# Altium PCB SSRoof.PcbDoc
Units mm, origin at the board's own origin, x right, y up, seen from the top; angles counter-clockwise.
Board outline 100 x 115 mm, 2 copper layers (Top Layer, Bottom Layer); 93 components, 75 nets, 327 pads, 36 vias.
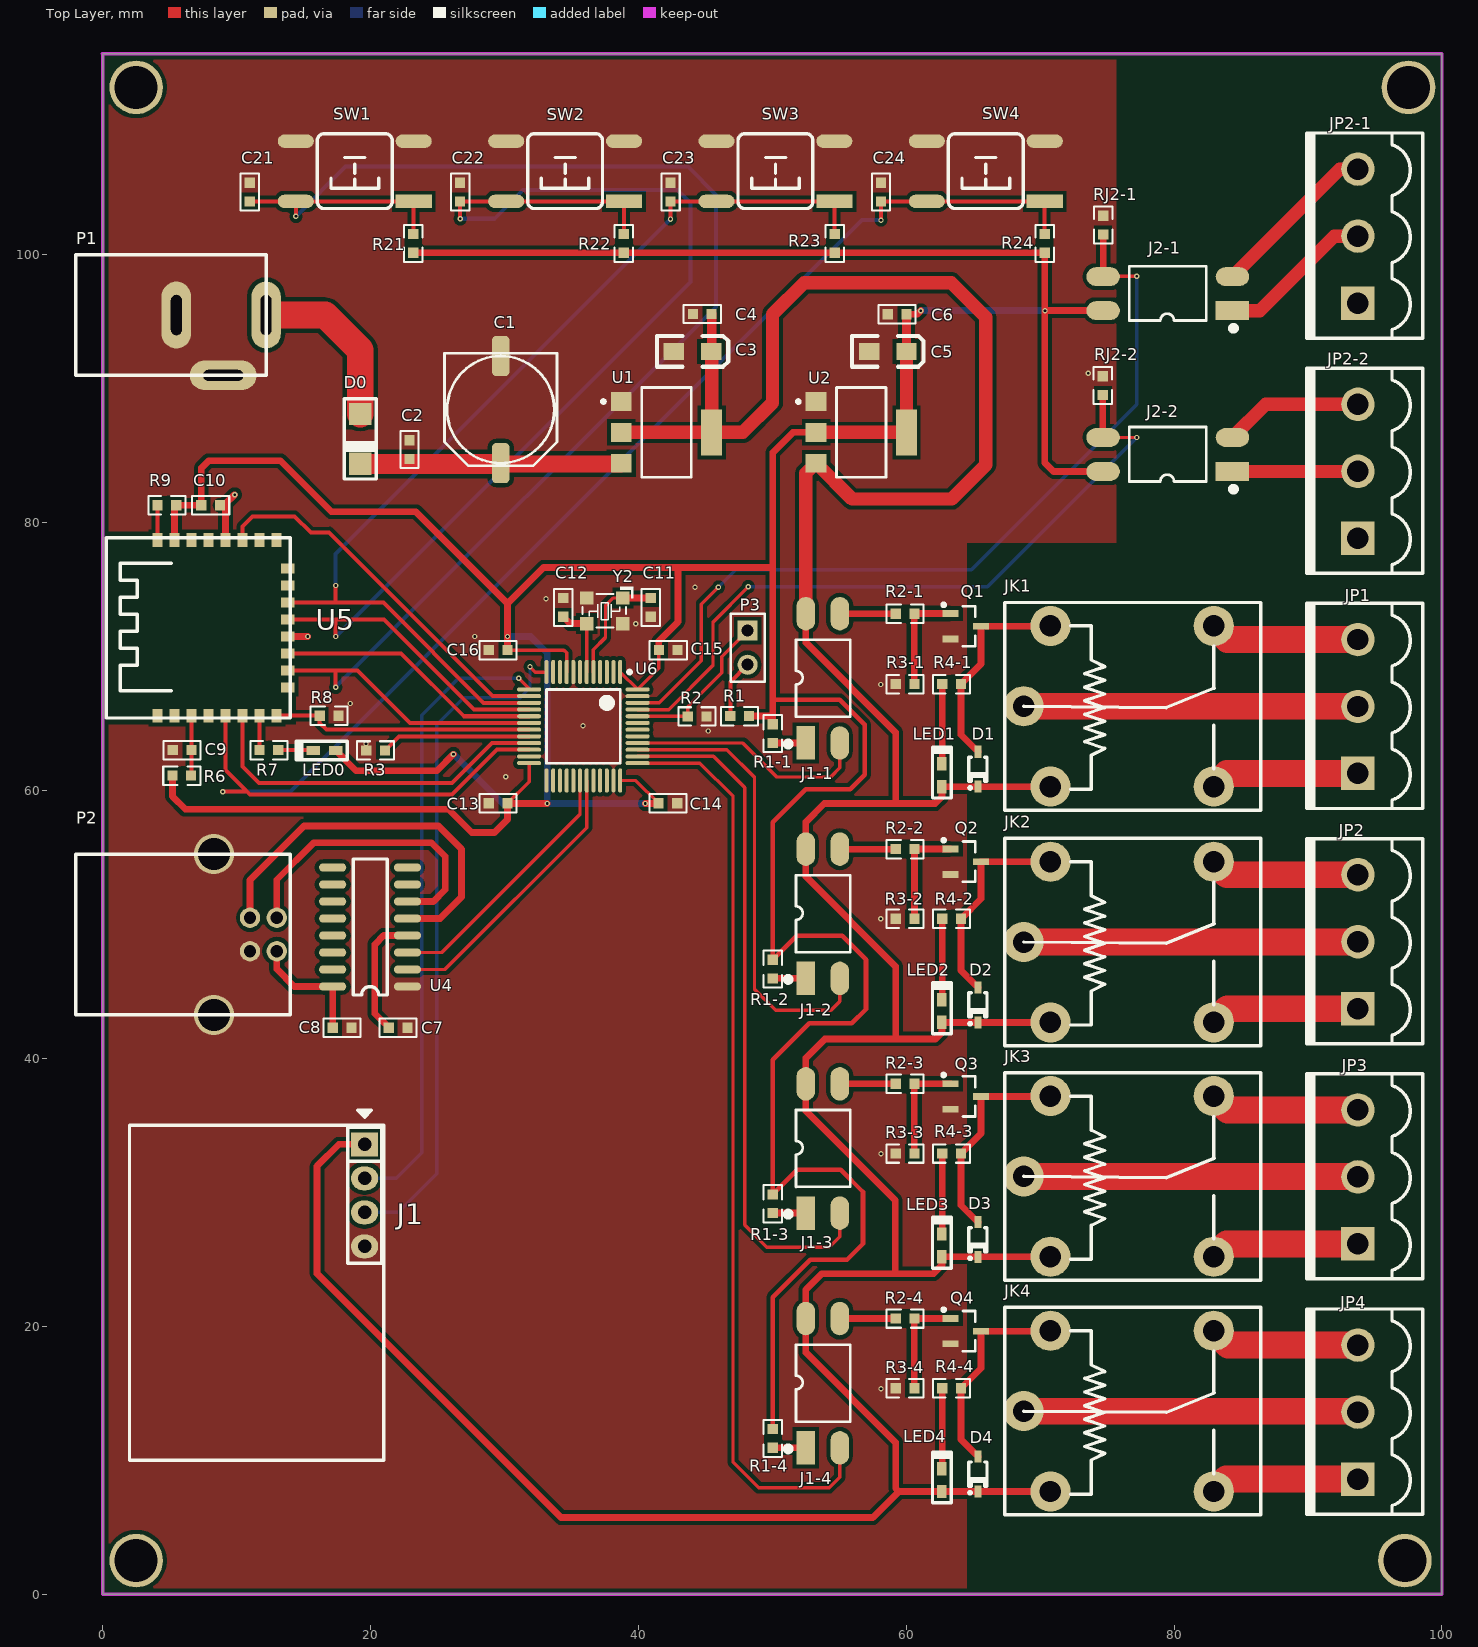
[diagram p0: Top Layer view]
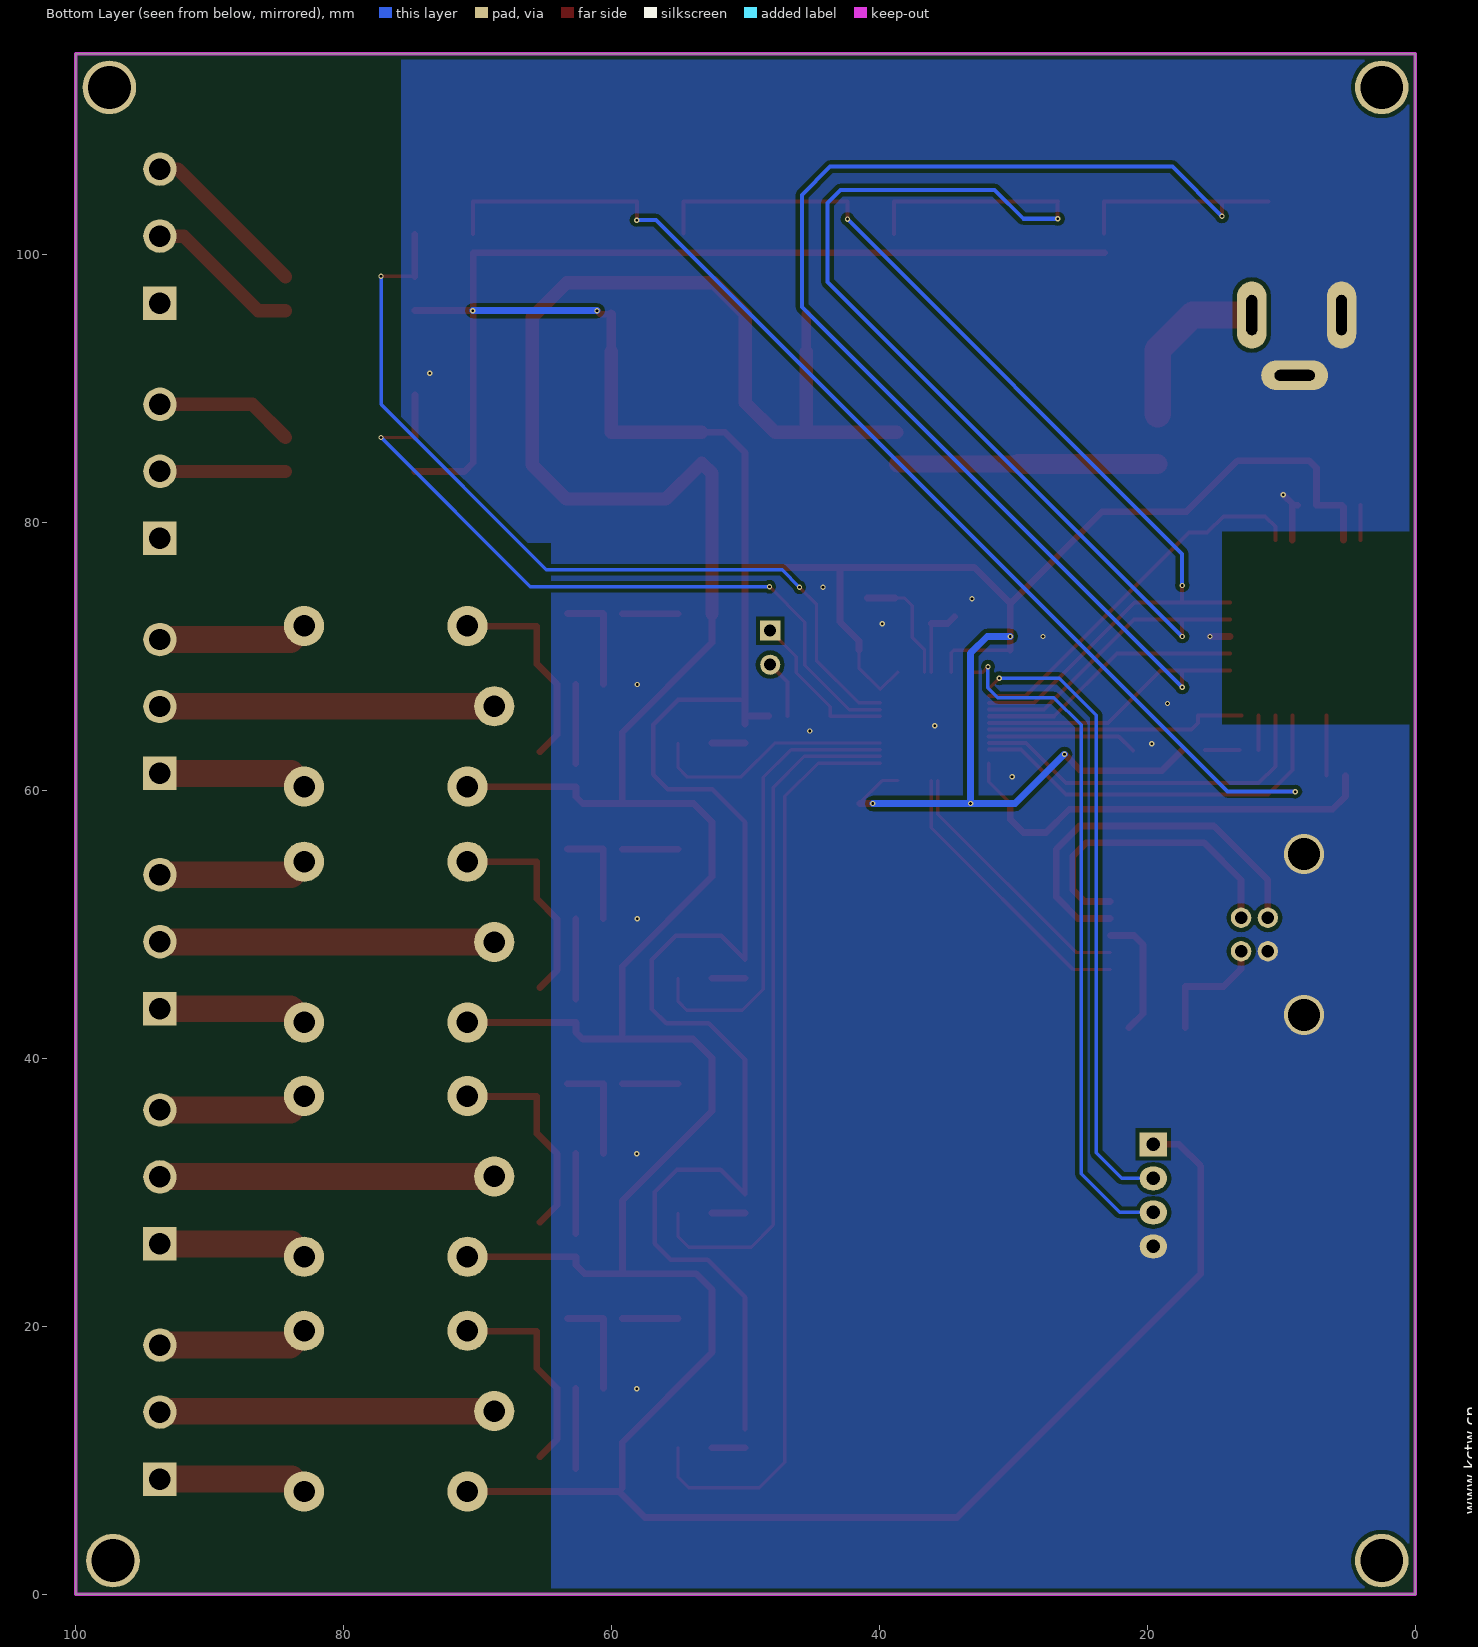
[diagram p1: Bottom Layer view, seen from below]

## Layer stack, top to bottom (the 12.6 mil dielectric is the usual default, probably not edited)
Top Solder: solder mask 0.0102, Solder Resist, Dk 3.5
Top Layer: signal copper 0.0356
Dielectric1: dielectric 0.32, FR-4, Dk 4.8
Bottom Layer: signal copper 0.0356
Bottom Solder: solder mask 0.0102, Solder Resist, Dk 3.5

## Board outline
0,0 0,115 100,115 100,0

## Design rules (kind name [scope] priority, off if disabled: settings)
Clearance Clearance_pyog [InPolygon] p1: gap=0.305
Clearance Clearance_mcu [InComponentClass('U7')] p2: gap=0.178
Clearance [All] p3: gap=0.178
HoleSize [All] p1: absolutevalues=TRUE maxlimit=25.4 minlimit=0.025 maxpercent=80.000 minpercent=20.000
MinimumSolderMaskSliver [All] p1: minsoldermaskwidth=0
PolygonConnect GNDVIA [IsVia] p1: connectstyle=Direct reliefconductorwidth=0.254 reliefentries=4 polygonreliefangle="90 Angle" airgapwidth=0.254
PolygonConnect [All] p2: connectstyle=Direct reliefconductorwidth=0.254 reliefentries=4 polygonreliefangle="90 Angle" airgapwidth=0.254
RoutingVias [All] p1: holewidth=0.711 width=1.27 viastyle="Through Hole" minholewidth=0.3 minwidth=0.45 maxholewidth=0.711 maxwidth=1.27
SilkToSilkClearance [All] p1: silktosilkclearance=0
SilkToSolderMaskClearance [IsPad] p1: minsilkscreentomaskgap=0 clearancetoexposedcopper=TRUE
SolderMaskExpansion [All] p1: expansion=0.102
Width [All] p1: maxlimit=3 minlimit=0.254 preferedwidth=0.254
25 further rules are at their usual default settings.

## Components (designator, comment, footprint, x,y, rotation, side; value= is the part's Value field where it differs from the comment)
C1 "470uF" CAP8 29.718,88.443 r90 top
C2 "100nF" 0603C 22.911,86.157 r270 top
C3 "10uF" 3216 45.441,92.786 r0 top
C4 "100nF" 0603C 44.069,95.58 r0 top
C5 "10uF" 3216 60.02,92.786 r0 top
C6 "100nF" 0603C 58.623,95.555 r0 top
C7 "100nF" 0603C 22.758,42.291 r180 top
C8 "100nF" 0603C 18.567,42.291 r180 top
C9 "100nF" 0603C 6.629,63.017 r180 top
C10 "100nF" 0603C 7.366,81.305 r0 top
C11 "20pF" 0603C 40.919,74.371 r270 top
C12 "20pF" 0603C 34.392,72.974 r90 top
C13 "100nF" 0603C 28.829,59.055 r0 top
C14 "100nF" 0603C 42.901,59.055 r180 top
C15 "100nF" 0603C 42.926,70.485 r180 top
C16 "100nF" 0603C 28.829,70.485 r0 top
C21 "1nF" 0603C 10.973,103.988 r90 top
C22 "1nF" 0603C 26.687,103.988 r90 top
C23 "1nF" 0603C 42.401,103.988 r90 top
C24 "1nF" 0603C 58.115,103.988 r90 top
D0 "M7" DO-214AC 19.228,86.258 r270 top
D1 "1N4148" SOD-323 65.354,61.595 r270 top
D2 "1N4148" SOD-323 65.354,43.993 r270 top
D3 "1N4148" SOD-323 65.354,26.467 r270 top
D4 "1N4148" SOD-323 65.354,8.966 r270 top
J1 "YS-RF34T" PIN-4-2.54-1.0 19.558,29.769 r270 top
J1-1 "TLP521-1" SOP4-W2.54_M 53.772,68.377 r90 top
J1-2 "TLP521-1" SOP4-W2.54_M 53.772,50.8 r90 top
J1-3 "TLP521-1" SOP4-W2.54_M 53.772,33.274 r90 top
J1-4 "TLP521-1" SOP4-W2.54_M 53.772,15.748 r90 top
J2-1 "TLP521-1" SOP4-W2.54_M 79.527,97.104 r180 top
J2-2 "TLP521-1" SOP4-W2.54_M 79.527,85.09 r180 top
JK1 "SRD-05VDC-SL-C" SRD-C_B 70.764,72.288 r0 top
JK2 "SRD-05VDC-SL-C" SRD-C_B 70.764,54.686 r0 top
JK3 "SRD-05VDC-SL-C" SRD-C_B 70.764,37.186 r0 top
JK4 "SRD-05VDC-SL-C" SRD-C_B 70.764,19.66 r0 top
JP1 "HDR-1X3" KF2EDGK5.0-LI-3P 93.726,66.274 r90 top
JP2 "HDR-1X3" KF2EDGK5.0-LI-3P 93.726,48.712 r90 top
JP2-1 "HDR-1X3" KF2EDGK5.0-LI-3P 93.726,101.397 r90 top
JP2-2 "HDR-1X3" KF2EDGK5.0-LI-3P 93.726,83.835 r90 top (schematic designator JP2-24)
JP3 "HDR-1X3" KF2EDGK5.0-LI-3P 93.726,31.151 r90 top
JP4 "HDR-1X3" KF2EDGK5.0-LI-3P 93.726,13.589 r90 top
LED0 "LED" LED-0603 16.561,62.992 r180 top
LED1 "LED" LED-0603 62.662,61.138 r90 top
LED2 "LED" LED-0603 62.662,43.536 r90 top
LED3 "LED" LED-0603 62.662,26.035 r90 top
LED4 "LED" LED-0603 62.662,8.509 r90 top
P1 "SOURCE" DC_5.5MM -2,100 r0 top
P2 "USB-B" USB-B 13,48 r0 top
P3 "BOOT0" HDR1X2 48.158,71.933 r270 top
Q1 "SS8050" SOT23-3N 64.44,72.263 r270 top
Q2 "SS8050" SOT23-3N 64.44,54.686 r270 top
Q3 "SS8050" SOT23-3N 64.44,37.16 r270 top
Q4 "SS8050" SOT23-3N 64.44,19.634 r270 top
R1 "4.7K" 0603R 46.863,65.557 r0 top
R1-1 "2K" 0603R 50.038,63.551 r90 top
R1-2 "2K" 0603R 50.038,45.974 r90 top
R1-3 "2K" 0603R 50.038,28.448 r90 top
R1-4 "2K" 0603R 50.038,10.922 r90 top
R2 "10K" 0603R 43.688,65.532 r0 top
R2-1 "1K" 0603R 60.604,73.203 r180 top
R2-2 "1K" 0603R 60.604,55.626 r180 top
R2-3 "1K" 0603R 60.604,38.1 r180 top
R2-4 "1K" 0603R 60.604,20.574 r180 top
R3 "10K" 0603R 19.685,62.992 r0 top
R3-1 "4.7K" 0603R 59.207,67.945 r0 top
R3-2 "4.7K" 0603R 59.207,50.419 r0 top
R3-3 "4.7K" 0603R 59.207,32.893 r0 top
R3-4 "4.7K" 0603R 59.207,15.367 r0 top
R4-1 "5K" 0603R 62.687,67.945 r0 top
R4-2 "5K" 0603R 62.687,50.419 r0 top
R4-3 "5K" 0603R 62.687,32.893 r0 top
R4-4 "5K" 0603R 62.687,15.367 r0 top
R6 "10K" 0603R 6.604,61.112 r180 top
R7 "1K" 0603R 11.709,63.017 r0 top
R8 "4.7K" 0603R 17.602,65.583 r180 top
R9 "10K" 0603R 4.089,81.305 r0 top
R21 "10K" 0603R 23.19,101.549 r270 top
R22 "10K" 0603R 38.913,101.549 r270 top
R23 "10K" 0603R 54.661,101.549 r270 top
R24 "10K" 0603R 70.333,101.549 r270 top
RJ2-1 "1K" 0603R 74.701,102.921 r270 top
RJ2-2 "1K" 0603R 74.676,90.932 r270 top
SW1 "6x6x5" "TSW SMD-6*6*6" 18.821,106.248 r180 top
SW2 "6x6x5" "TSW SMD-6*6*6" 34.527,106.248 r180 top
SW3 "6x6x5" "TSW SMD-6*6*6" 50.233,106.248 r180 top
SW4 "6x6x5" "TSW SMD-6*6*6" 65.938,106.248 r180 top
U1 "AMS1117-5.0" SOT223 42.088,86.741 r270 top
U2 "AMS1117-3.3" SOT223 56.642,86.741 r270 top
U4 "CH340C" SO-16 22.758,45.364 r180 top
U5 "PSF-B04" PSF-B04 14,78.873 r180 top
U6 "STM32F103C8T6" LQFP48_N 35.89,64.795 r180 top
Y2 "8MHz  无源" X3225 38.811,74.397 r180 top

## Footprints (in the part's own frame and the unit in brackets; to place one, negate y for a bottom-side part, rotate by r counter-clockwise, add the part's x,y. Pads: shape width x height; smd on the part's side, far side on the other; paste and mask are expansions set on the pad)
0603C [mil]
  rect 30x30 smd: 1(0,0) 2(55,0)
  silkscreen extent -27,-27 82,27, body extent -4,-16 59,16, height 12
0603R [mil]
  rect 30x30 smd: 1(0,0) 2(55,0)
  silkscreen extent -27,-27 82,27, body extent -4,-18 58,16, height 18
3216 [mil]
  rect 60x50 smd: 1(0,0) 2(-110,0)
  silkscreen extent -160,-45 50,45, body extent -151,-35 38,36, height 73
CAP8 [mm] "直径8mm（蒜米工坊）"
  rrect50% 3x1.3 smd: 1(-4,0) 2(4,0)
  silkscreen extent -4.2,-4.2 4.2,4.2, body extent -4.52,-4.22 4.48,4.08, height 10.5
DC_5.5MM [mm]
  oval 2.2x5 hole 0.8 slot 3 at 90 deg: 1(14.2,-4.5) 2(7.5,-4.5)
  oval 5x2.2 hole 0.8 slot 3 at 0 deg: 3(11,-9)
  silkscreen extent 0,-9 14.2,0, body extent -0.1,-8.88 14.1,-0.12, height 10.82
DO-214AC [mm]
  rect 1.655x1.67 smd: 1(1.865,0) 2(-1.865,0)
  silkscreen extent -3,-1.2 3,1.2, body extent -2.74,-1.4 2.74,1.4, height 2.3
HDR1X2 [mm] "Connector; Header; 2 Position"
  rect 1.5x1.5 hole 0.9: 1(0,0)
  round 1.5 hole 0.9: 2(2.54,0)
  silkscreen extent -1.27,-1.27 3.81,1.27, body extent -1.27,-1.27 3.81,1.27, height 7.58
KF2EDGK5.0-LI-3P [mm] "立插端子"
  rect 2.5x2.5 hole 1.6: 1(-5,0)
  round 2.5 hole 1.6: 2(0,0) 3(5,0)
  silkscreen extent -7.62,-4.83 7.7,3.81, body extent -7.54,-4.75 7.54,3.75, height 11.25
LED-0603 [mm] "LED, SMD, 0603"
  rect 1x0.7 smd: 1(-0.85,0) 2(0.85,0)
  silkscreen extent -1.7,-0.7 2.1,0.7, body extent -1.03,-0.46 1.03,0.45, height 0.85
LQFP48_N [mm]
  oval 0.3x1.8 smd: 1(-2.75,-4.05) 2(-2.25,-4.05) 3(-1.75,-4.05) 4(-1.25,-4.05) 5(-0.75,-4.05) 6(-0.25,-4.05) 7(0.25,-4.05) 8(0.75,-4.05) 9(1.25,-4.05) 10(1.75,-4.05) 11(2.25,-4.05) 12(2.75,-4.05) 25(2.75,4.05) 26(2.25,4.05) 27(1.75,4.05) 28(1.25,4.05) 29(0.75,4.05) 30(0.25,4.05) 31(-0.25,4.05) 32(-0.75,4.05) 33(-1.25,4.05) 34(-1.75,4.05) 35(-2.25,4.05) 36(-2.75,4.05)
  oval 1.8x0.3 smd: 13(4.05,-2.75) 14(4.05,-2.25) 15(4.05,-1.75) 16(4.05,-1.25) 17(4.05,-0.75) 18(4.05,-0.25) 19(4.05,0.25) 20(4.05,0.75) 21(4.05,1.25) 22(4.05,1.75) 23(4.05,2.25) 24(4.05,2.75) 37(-4.05,2.75) 38(-4.05,2.25) 39(-4.05,1.75) 40(-4.05,1.25) 41(-4.05,0.75) 42(-4.05,0.25) 43(-4.05,-0.25) 44(-4.05,-0.75) 45(-4.05,-1.25) 46(-4.05,-1.75) 47(-4.05,-2.25) 48(-4.05,-2.75)
  silkscreen extent -3.58,-4.17 2.75,2.75, body extent -4.5,-4.5 4.5,4.5, height 1.5
PIN-4-2.54-1.0 [mil] "Pin Header"
  rect 70x80 hole 39.37: 1(-150,0)
  oval 70x80 hole 39.37: 2(-50,0) 3(50,0) 4(150,0)
  silkscreen extent -250,-50 200,50, body extent -200,-50 200,50, height 398
PSF-B04 [mm] "物联网开关芯片"
  rect 0.76x1.02 smd: 1(9.91,13.29) 2(8.64,13.29) 3(7.37,13.29) 4(6.1,13.29) 5(4.83,13.29) 6(3.56,13.29) 7(2.29,13.29) 8(1.02,13.29) 17(1.02,0.17) 18(2.29,0.17) 19(3.56,0.17) 20(4.83,0.17) 21(6.1,0.17) 22(7.37,0.17) 23(8.64,0.17) 24(9.91,0.17)
  rect 1.02x0.76 smd: 9(0.17,11.18) 10(0.17,9.91) 11(0.17,8.64) 12(0.17,7.37) 13(0.17,6.1) 14(0.17,4.83) 15(0.17,3.56) 16(0.17,2.29)
  silkscreen extent 0,0 13.72,13.46
SO-16 [mil]
  oval 80x24 smd: 1(0,0) 2(0,-50) 3(0,-100) 4(0,-150) 5(0,-200) 6(0,-250) 7(0,-300) 8(0,-350) 9(220,-350) 10(220,-300) 11(220,-250) 12(220,-200) 13(220,-150) 14(220,-100) 15(220,-50) 16(220,0)
  silkscreen extent 60,-375 160,25, body extent -12,-377 226,29, height 77
SOD-323 [mm] "SOD-323"
  rect 0.9x0.5 smd: 1(-1.3,0) 2(1.3,0)
  silkscreen extent -0.9,-0.67 1.49,0.67, body extent -1.35,-0.62 1.35,0.63, height 1.1
SOP4-W2.54_M [mm] "6.5*4.58*3.5mm（长宽高）"
  rect 2.5x1.4 smd: 1(-4.826,1.27)
  oval 2.5x1.4 smd: 2(-4.826,-1.27) 3(4.826,-1.27) 4(4.826,1.27)
  silkscreen extent -5.06,-2.05 2.87,2.74, body extent -5,-2.29 5,2.29, height 3.83
SOT23-3N [mm] "3x1.3x1mm(长宽高)"
  rect 0.5x1.2 smd: 1(-0.95,-1.143) 2(0.95,-1.143) 3(0,1.143)
  silkscreen extent -1.72,-1.78 1.5,0.7, body extent -1.5,-1.2 1.5,1.2, height 1.05
SOT223 [mm] "SOT-223/SC-73; 4 Leads; Body 6.7 x 7.3 mm, inc. leads (LxW max)"
  rect 1.4x1.55 smd: 1(-2.3,-3.375) 2(0,-3.375) 3(2.3,-3.375)
  rect 3.45x1.55 smd: 4(0,3.375)
  silkscreen extent -3.35,-4.82 3.35,1.85, body extent -3.25,-3.53 3.25,3.43, height 1.7
SRD-C_B [mm] "单刀双投"
  round 3 hole 1.6: 1(0,0) 2(0,-12) 3(-2,-6) 4(12.2,0) 5(12.2,-12)
  silkscreen extent -3.4,-13.75 15.7,1.75, body extent -3.4,-13.75 15.7,1.75, height 15.6
"TSW SMD-6*6*6" [mm] "6*6*6mm"
  rect 2.7x1 smd: 1(-4.4,2.261)
  oval 2.7x1 smd: 2(-4.4,-2.239) 3(4.4,-2.239) 4(4.4,2.261)
  silkscreen extent -2.79,-2.79 2.79,2.79, body extent -4.5,-3 4.5,3, height 5.95
USB-B [mm]
  round 1.524 hole 0.92: 1(0,0) 2(0,2.5) 3(-2,2.5) 4(-2,0)
  round 3 hole 2.4: 5(-4.7,7.25) 6(-4.7,-4.75)
  silkscreen extent -15,-4.75 1,7.25
X3225 [mm]
  rect 1x1 smd: 1(-0.025,0.025) 2(2.667,0.025) 3(2.667,1.93) 4(-0.025,1.93)
  silkscreen extent -0.81,-0.84 3,2.21, body extent -0.23,-0.29 2.97,2.21, height 0.72

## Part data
C1: library part C470UF016S, "470UF      16V      CD10X10D5"
C2 C4 C6 C8 C9 C10 C11 C12 C13 C14 C15 C16 C21 C22 C23 C24: library part Cap, "Capacitor"
C3 C5: library part CAP2
C7: library part C
D0: library part Diode, "High Conductance Fast Diode"
D1 D2 D3 D4: "高速开关二极管"
J1: library part HDR1x4, "Connector"
J1-1 J1-2 J1-3 J1-4 J2-1 J2-2: "1路开关光耦"
JK1 JK2 JK3 JK4: "5V一组转换"
JP1 JP2 JP2-1 JP2-2 JP3 JP4: library part "Header 3", "3P接插件"
P3: library part MHDR1X2, "Header, 2-Pin"
Q1 Q2 Q3 Q4: library part 8050-SMD, "高频放大-NPN型"
R1 R3 R3-1 R3-2 R3-3 R3-4 R8: library part R
R1-1 R1-2 R1-3 R1-4 R2 R2-1 R2-2 R2-3 R2-4 R4-1 R4-2 R4-3 R4-4 R6 R7 R9 R21 R22 R23 R24 RJ2-1 RJ2-2: library part RES, "Resistor"
SW1 SW2 SW3 SW4: library part "TSW SMD-6x6", "贴片6x6轻触开关"
U1 U2: library part AMS1117
U4: library part CH340G, "USB2UART"
U6: "STM32 ARM-based 32-bit MCU Performance Line with 64 kB Flash, 20 kB Internal RAM, -40 to +85癈 Temperature, 48-Pin LQFP, Tray"
Y2: library part XTAL_1, "Crystal Oscillator"

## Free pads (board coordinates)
  round 4 hole 3.2: 0(2.5,2.5) 1(97.231,2.5) 2(97.5,112.5) 3(2.5,112.5)

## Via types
v1: diameter 0.4, hole 0.2, Top Layer to Bottom Layer, 36 vias

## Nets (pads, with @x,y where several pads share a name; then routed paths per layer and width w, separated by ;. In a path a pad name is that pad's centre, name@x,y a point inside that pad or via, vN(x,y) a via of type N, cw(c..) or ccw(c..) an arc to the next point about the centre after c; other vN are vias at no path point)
BOOT0: P3.1 R2.1 U6.44 | length 12
  Top Layer w0.254: U6.44 R2.1@43.675,65.545 ; R2.1 43.688,66.243 46.228,68.783 46.228,70.002 P3.1
BOOT1: R3.2 U6.20 | length 11.2
  Top Layer w0.305: R3.2 22.135,64.045 U6.20
D3V3: C5.1 C6.2 C10.1 C13.2 C14.2 C15.2 C16.2 J2-1.4 J2-2.4 LED0.1 R1-1.2 R1-2.2 R1-3.2 R1-4.2 R1.2 R6.2 R9.2 R21.2 R22.2 R23.2 R24.2 U2.2 U2.4 U5.23 U6.1 U6.9 U6.24 U6.36 U6.48 | length 372.9
  Top Layer w0.254: C13.2 31.84,60.669 U6.24 ; C16.2 34.442,70.485 34.64,70.287 U6.9 ; U6.36 39.813,60.745 C14.2 ; U6.1 U6.48 41.529,69.134 C15.2
  Top Layer w0.35: R1-4.2 50.038,22.174 52.832,24.968 55.575,24.968 56.769,26.162 56.769,30.023 55.118,31.674 51.867,31.674 R1-3.2 50.038,39.903 52.756,42.621 55.931,42.621 56.998,43.688 56.998,47.371 55.22,49.149 51.816,49.149 R1-2.2 50.038,57.633 52.502,60.096 55.804,60.096 56.896,61.189 56.896,64.922 55.042,66.777 50.038,66.777
  Top Layer w0.5: R6.2 5.207,59.563 6.172,58.598 25.832,58.598 27.559,56.871 29.261,56.871 30.226,57.836 C13.2 ; C10.1 7.366,84.074 7.925,84.633 13.259,84.633 17.069,80.823 23.368,80.823 30.226,73.965 ; LED0.1 18.935,61.468 24.943,61.468 v1(26.187,62.713) ; R21.2 R22.2 R23.2 R24.2 70.333,84.48 70.993,83.82 J2-2.4 ; C16.2 v1(30.226,71.501) 30.226,73.965 ; C13.2@30.251,59.03 v1(33.198,59.03) ; v1(40.513,59.03) C14.2@41.478,59.03 ; C15.2 41.529,71.171 42.951,72.593 42.951,76.657 ; R1.2 50.013,65.557 ; R1-1.2 50.038,76.657 ; U2.2 51.537,86.741 50.038,85.242 50.038,76.657 ; C6.2 60.808,95.555 v1(61.087,95.834) ; v1(70.358,95.834) J2-1.4 ; 30.226,73.965 32.918,76.657 50.038,76.657
  Top Layer w0.508: U5.23 5.36,81.179 R9.2 C10.1
  Top Layer w0.7: C5.1 C6.2
  Top Layer w1: U2.2 U2.4 C5.1@60.017,92.783
  Bottom Layer w0.5: v1(26.187,62.713) 29.87,59.03 v1(33.198,59.03) ; v1(30.226,71.501) 31.953,71.501 33.198,70.256 v1(33.198,59.03) ; v1(40.513,59.03) v1(33.198,59.03) ; v1(61.087,95.834) v1(70.358,95.834)
D5V0: C3.1 C4.2 D1.2 D2.2 D3.2 D4.2 J1-1.4 J1-2.4 J1-3.4 J1-4.4 J1.1 JK1.2 JK2.2 JK3.2 JK4.2 LED1.1 LED2.1 LED3.1 LED4.1 U1.2 U1.4 U2.3 | length 290.4
  Top Layer w0.5: J1.1 17.628,33.579 16.002,31.953 16.002,23.927 34.214,5.715 57.504,5.715 59.448,7.659 ; J1-1.4 52.502,71.044 59.207,64.338 59.207,59.03 ; JK4.2@70.764,7.659 LED4.1 59.448,7.659 ; JK3.2@70.764,25.185 LED3.1 62.662,24.562 62.027,23.927 59.182,23.927 ; JK2.2@70.764,42.686 LED2.1 62.662,41.935 62.179,41.453 59.207,41.453 ; JK1.2@70.764,60.288 LED1.1 62.662,59.538 62.154,59.03 59.207,59.03 ; 59.182,23.927 59.182,29.388 52.502,36.068 J1-3.4 52.502,40.03 53.924,41.453 59.207,41.453 ; 59.182,23.927 53.696,23.927 52.502,22.733 J1-4.4 52.502,18.034 59.207,11.328 59.207,7.899 59.448,7.659 ; 59.207,41.453 59.207,46.863 52.502,53.569 J1-2.4 52.502,57.658 53.873,59.03 59.207,59.03
  Top Layer w0.7: C3.1@45.466,92.812 C4.2
  Top Layer w1: U1.2 U1.4 ; C3.1@45.463,92.764 U1.4 ; J1-1.4 52.502,83.676 U2.3 55.945,81.763 63.398,81.763 65.938,84.303 65.938,95.326 63.348,97.917 52.375,97.917 50.013,95.555 50.013,88.951 47.803,86.741 U1.4
D12V0: C1.1 C2.2 D0.1 U1.3 | length 19.4
  Top Layer w1.27: C1.1@29.669,84.393 U1.3@38.665,84.393
  Top Layer w1.5: D0.1 C1.1@29.669,84.393
EGND: J2-1.2 JP2-1.3 | length 12.7
  Top Layer w1: J2-1.2 92.376,106.397 JP2-1.3
EGND2: J2-2.2 JP2-2.3 | length 10.4
  Top Layer w1: J2-2.2 86.829,88.835 JP2-2.3
ESIGN: J2-1.1 JP2-1.2 | length 11.7
  Top Layer w1: J2-1.1 86.385,95.834 91.948,101.397 JP2-1.2
ESIGN2: J2-2.1 JP2-2.2 | length 9.4
  Top Layer w1: J2-2.1 JP2-2.2@93.711,83.82
EVCC: JP2-1.1
EVCC2: JP2-2.1
GND: C1.2 C2.1 C3.2 C4.1 C5.2 C6.1 C7.1 C8.1 C9.2 C10.2 C11.2 C12.2 C13.1 C14.1 C15.1 C16.1 C21.2 C22.2 C23.2 C24.2 J1.4 P1.2 P1.3 P2.4 P2.5 P2.6 Q1.2 Q2.2 Q3.2 Q4.2 R2.2 R3-1.1 R3-2.1 R3-3.1 R3-4.1 R3.1 R8.1 RJ2-1.1 RJ2-2.1 SW1.2 SW1.3 SW2.2 SW2.3 SW3.2 SW3.3 SW4.2 SW4.3 U1.1 U2.1 U4.1 U5.12 U5.20 U6.8 U6.23 U6.35 U6.47 Y2.2 Y2.4 | length 6.5
  Top Layer w0.5: C10.2 9.068,81.305 v1(9.855,82.093) ; U5.20 9.17,81.408 v1@9.83,82.067 ; U5.12 v1(15.319,71.503)
  other v1: 58.115,15.342 58.115,32.868 58.09,50.419 30.099,61.036 19.66,63.5 45.212,64.44 35.865,64.846 18.491,66.497 58.09,67.92 27.788,71.501 39.802,72.441 33.096,74.32 44.221,75.184 73.584,91.161
LIMIT1: J2-1.3 RJ2-1.2 U6.46 | length 64.2
  Top Layer w0.254: U6.46 41.552,66.545 44.704,69.698 44.704,73.914 v1(45.974,75.184) ; J2-1.3@74.727,98.4 v1(77.216,98.4)
  Top Layer w0.5: J2-1.3 RJ2-1.2
  Bottom Layer w0.254: v1(45.974,75.184) 47.269,76.479 64.872,76.479 77.216,88.824 v1(77.216,98.4)
LIMIT2: J2-2.3 RJ2-2.2 U6.45 | length 53.2
  Top Layer w0.254: U6.45 42.271,66.045 45.568,69.342 45.568,72.568 v1(48.209,75.209) ; J2-2.3 v1(77.216,86.36)
  Top Layer w0.5: J2-2.3@74.676,86.385 RJ2-2.2
  Bottom Layer w0.254: v1(48.209,75.209) 66.065,75.209 v1(77.216,86.36)
NetC7_2: C7.2 U4.4 | length 9.4
  Top Layer w0.508: C7.2 20.32,43.332 20.32,48.514 20.98,49.174 U4.4
NetC9_1: C9.1 R6.1 U5.3 | length 4.4
  Top Layer w0.3: R6.1@6.63,61.138 U5.3
NetD0_1: D0.2 P1.1 | length 12.9
  Top Layer w2: P1.1 16.616,95.5 19.228,92.888 D0.2
NetD1_1: D1.1 JK1.1 Q1.3 R4-1.2 | length 15.7
  Top Layer w0.5: D1.1 64.084,64.165 R4-1.2 65.583,69.444 Q1.3 JK1.1@70.739,72.263
NetD2_1: D2.1 JK2.1 Q2.3 R4-2.2 | length 15.7
  Top Layer w0.5: D2.1 64.084,46.563 R4-2.2 65.583,51.918 Q2.3 JK2.1
NetD3_1: D3.1 JK3.1 Q3.3 R4-3.2 | length 15.7
  Top Layer w0.5: D3.1 64.084,29.037 R4-3.2 65.583,34.392 Q3.3 JK3.1@70.739,37.16
NetD4_1: D4.1 JK4.1 Q4.3 R4-4.2 | length 15.7
  Top Layer w0.5: D4.1 64.084,11.536 R4-4.2 65.583,16.866 Q4.3 JK4.1@70.739,19.634
NetJ1-1_1: J1-1.1 R1-1.1 | length 2.5
  Top Layer w0.5: R1-1.1 J1-1.1
NetJ1-1_3: J1-1.3 R2-1.2 | length 4.2
  Top Layer w0.5: J1-1.3 R2-1.2
NetJ1-2_1: J1-2.1 R1-2.1 | length 2.5
  Top Layer w0.5: R1-2.1 J1-2.1
NetJ1-2_3: J1-2.3 R2-2.2 | length 4.2
  Top Layer w0.5: J1-2.3 R2-2.2
NetJ1-3_1: J1-3.1 R1-3.1 | length 2.5
  Top Layer w0.5: R1-3.1 J1-3.1
NetJ1-3_3: J1-3.3 R2-3.2 | length 4.2
  Top Layer w0.5: J1-3.3 R2-3.2
NetJ1-4_1: J1-4.1 R1-4.1 | length 2.5
  Top Layer w0.5: R1-4.1 J1-4.1
NetJ1-4_3: J1-4.3 R2-4.2 | length 4.2
  Top Layer w0.5: J1-4.3 R2-4.2
NetJK1_3: JK1.3 JP1.2 | length 24.9
  Top Layer w2: JK1.3 JP1.2@93.711,66.288
NetJK1_4: JK1.4 JP1.3 | length 11.2
  Top Layer w2: JK1.4 83.979,71.274 JP1.3
NetJK1_5: JK1.5 JP1.1 | length 11.2
  Top Layer w2: JK1.5 83.95,61.274 JP1.1
NetJK2_3: JK2.3 JP2.2 | length 24.9
  Top Layer w2: JK2.3 JP2.2@93.7,48.686
NetJK2_4: JK2.4 JP2.3 | length 11.2
  Top Layer w2: JK2.4 83.938,53.712 JP2.3
NetJK2_5: JK2.5 JP2.1 | length 11.2
  Top Layer w2: JK2.5 83.99,43.712 JP2.1
NetJK3_3: JK3.3 JP3.2 | length 24.9
  Top Layer w2: JK3.3 JP3.2@93.691,31.186
NetJK3_4: JK3.4 JP3.3 | length 11.2
  Top Layer w2: JK3.4 83.999,36.151 JP3.3
NetJK3_5: JK3.5 JP3.1 | length 11.2
  Top Layer w2: JK3.5 83.929,26.151 JP3.1
NetJK4_3: JK4.3 JP4.2 | length 24.9
  Top Layer w2: JK4.3 JP4.2@93.655,13.66
NetJK4_4: JK4.4 JP4.3 | length 11.2
  Top Layer w2: JK4.4 84.035,18.589 JP4.3
NetJK4_5: JK4.5 JP4.1 | length 11.1
  Top Layer w2: JK4.5 83.894,8.589 JP4.1
NetLED0_2: LED0.2 R7.2 | length 2.6
  Top Layer w0.3: R7.2 LED0.2@15.685,63.017
NetLED1_2: LED1.2 R4-1.1 | length 5.9
  Top Layer w0.5: LED1.2@62.687,62.013 R4-1.1
NetLED2_2: LED2.2 R4-2.1 | length 6
  Top Layer w0.5: LED2.2@62.687,44.411 R4-2.1
NetLED3_2: LED3.2 R4-3.1 | length 6
  Top Layer w0.5: LED3.2@62.687,26.91 R4-3.1
NetLED4_2: LED4.2 R4-4.1 | length 6
  Top Layer w0.5: LED4.2@62.687,9.384 R4-4.1
NetP2_2: P2.2 U4.6 | length 22.6
  Top Layer w0.5: P2.2 13,53.335 15.773,56.109 24.536,56.109 25.578,55.067 25.578,52.603 24.689,51.714 U4.6
NetP2_3: P2.3 U4.5 | length 29.3
  Top Layer w0.5: P2.3 11,53.316 15.037,57.353 25.07,57.353 26.797,55.626 26.797,52.045 25.197,50.444 U4.5
NetP3_2: P3.2 R1.1 | length 4.4
  Top Layer w0.3: R1.1 46.863,68.097 P3.2
NetQ1_1: Q1.1 R2-1.1 R3-1.2 | length 7.9
  Top Layer w0.5: R3-1.2 R2-1.1 ; R2-1.1@60.615,73.213 Q1.1
NetQ2_1: Q2.1 R2-2.1 R3-2.2 | length 7.9
  Top Layer w0.5: R3-2.2@60.615,50.429 60.615,55.636 Q2.1
NetQ3_1: Q3.1 R2-3.1 R3-3.2 | length 7.9
  Top Layer w0.5: R3-3.2 R2-3.1 ; R2-3.1@60.615,38.11 Q3.1
NetQ4_1: Q4.1 R2-4.1 R3-4.2 | length 7.9
  Top Layer w0.5: R3-4.2 R2-4.1 ; R2-4.1@60.615,20.584 Q4.1
NetR7_1: R7.1 U5.7 | length 2.6
  Top Layer w0.3: R7.1 U5.7
NetR9_1: R9.1 U5.24 | length 2.6
  Top Layer w0.3: U5.24 R9.1
O1: U5.6 U6.21 | length 26.9
  Top Layer w0.3: U5.6 10.44,61.798 11.684,60.554 26.086,60.554 29.078,63.545 U6.21
O2: U5.19 U6.14 | length 28.3
  Top Layer w0.3: U5.19 10.44,79.706 11.201,80.467 14.326,80.467 15.545,79.248 16.891,79.248 29.094,67.045 U6.14
O3: U5.11 U6.17 | length 20
  Top Layer w0.3: U5.11 22.273,70.233 26.961,65.545 U6.17
O4: R8.2 U5.8 U6.19 | length 19.6
  Top Layer w0.3: U5.8 R8.2 16.205,65.049 16.709,64.545 U6.19
OSC_IN: C11.1 U6.5 Y2.1 | length 8.9
  Top Layer w0.254: U6.5 36.64,70.524 37.541,71.425 37.541,73.812 38.1,74.371 Y2.1
  Top Layer w0.5: Y2.1 C11.1
OSC_OUT: C12.1 U6.6 Y2.3 | length 5.6
  Top Layer w0.254: U6.6 Y2.3@36.14,72.462
  Top Layer w0.5: C12.1 34.9,72.466 Y2.3
RELAY1: J1-1.2 U6.40 | length 18.3
  Top Layer w0.254: U6.40 47.808,63.545 50.343,61.011 54.356,61.011 55.042,61.697 J1-1.2
RELAY2: J1-2.2 U6.39 | length 34.4
  Top Layer w0.254: U6.39 46.606,63.045 48.666,60.985 48.666,45.161 50.241,43.586 54.381,43.586 55.042,44.247 J1-2.2
RELAY3: J1-3.2 U6.38 | length 51.5
  Top Layer w0.254: U6.38 45.608,62.545 47.93,60.223 47.93,27.559 49.581,25.908 54.254,25.908 55.042,26.695 J1-3.2
RELAY4: J1-4.2 U6.37 | length 69.1
  Top Layer w0.254: U6.37 44.584,62.045 47.066,59.563 47.066,9.855 48.971,7.95 54.254,7.95 55.042,8.738 J1-4.2
RESET: U6.7
RXD: U4.3 U6.30 | length 19.7
  Top Layer w0.254: U4.3 25.324,47.904 35.64,58.221 U6.30
RXD2: J1.3 U6.12 | length 51.2
  Top Layer w0.254: v1(31.902,69.24) 32.297,68.845 U6.12
  Bottom Layer w0.254: J1.3 22.073,28.499 24.943,31.369 24.943,64.897 26.975,66.929 31.166,66.929 31.902,67.666 v1(31.902,69.24)
S1: C21.1 R21.1 SW1.1 SW1.4 U5.10 U6.18 | length 118.9
  Top Layer w0.3: C21.1 SW1.4 SW1.1 R21.1@23.221,101.58 ; U5.10 17.399,68.963 ; v1(14.427,102.87) SW1.4@14.427,103.982 ; v1(17.399,67.716) 17.399,68.963 ; U6.18 22.94,65.045 19.022,68.963 17.399,68.963
  Bottom Layer w0.3: v1(14.427,102.87) 18.136,106.578 43.688,106.578 45.796,104.47 45.796,96.114 v1(17.399,67.716)
S2: C22.1 R22.1 SW2.1 SW2.4 U5.13 U6.16 | length 99.9
  Top Layer w0.3: U5.13 17.399,72.773 ; v1(17.399,71.501) 17.399,72.773 ; C22.1 SW2.1 38.913,103.973 R22.1 ; v1(26.695,102.692) C22.1@26.695,103.979 ; U6.16 27.731,66.045 21.003,72.773 17.399,72.773
  Bottom Layer w0.3: v1(17.399,71.501) 17.424,71.501 43.891,97.968 43.891,103.861 42.926,104.826 31.394,104.826 29.261,102.692 v1(26.695,102.692)
S3: C23.1 R23.1 SW3.1 SW3.4 U5.14 U6.15 | length 76
  Top Layer w0.3: U5.14 17.399,74.043 ; v1(17.399,75.311) 17.399,74.043 ; U6.15 28.451,66.545 20.953,74.043 17.399,74.043 ; v1(42.393,102.667) C23.1@42.393,103.979 ; C23.1 SW3.1 R23.1@54.633,101.577
  Bottom Layer w0.3: v1(17.399,75.311) 17.399,77.673 v1(42.393,102.667)
S4: C24.1 R24.1 SW4.1 SW4.4 U5.5 U6.22 | length 113.6
  Top Layer w0.3: v1(8.966,59.919) 10.77,59.919 ; U5.5 9.17,61.518 10.77,59.919 ; U6.22 29.441,63.045 26.086,59.69 10.998,59.69 10.77,59.919 ; v1(58.115,102.591) C24.1 SW4.1 70.333,103.982 R24.1
  Bottom Layer w0.3: v1(8.966,59.919) 14.021,59.919 56.693,102.591 v1(58.115,102.591)
TXD: U4.2 U6.31 | length 21.3
  Top Layer w0.254: U4.2 25.552,46.634 36.14,57.222 U6.31
TXD2: J1.2 U6.13 | length 47.3
  Top Layer w0.254: v1(31.064,68.377) 31.84,67.601 U6.13
  Bottom Layer w0.254: J1.2 21.92,31.039 23.825,32.944 23.825,65.634 26.568,68.377 v1(31.064,68.377)
VBUS: C8.2 P2.1 U4.16 | length 9.1
  Top Layer w0.508: P2.1 13,46.665 14.3,45.364 U4.16 C8.2
pads on no net: U4.7 U4.8 U4.9 U4.10 U4.11 U4.12 U4.13 U4.14 U4.15 U5.1 U5.2 U5.4 U5.9 U5.15 U5.16 U5.17 U5.18 U5.21 U5.22 U6.2 U6.3 U6.4 U6.10 U6.11 U6.25 U6.26 U6.27 U6.28 U6.29 U6.32 U6.33 U6.34 U6.41 U6.42 U6.43

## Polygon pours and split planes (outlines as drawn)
GND on Top Layer "Bottom Layer-No Net" (solid, remove dead copper, pour order 12): -0.127,0.203 99.644,0.203 99.847,0 100,0.153 100,115 -0.02,115
GND on Bottom Layer "Bottom Layer-No Net" (solid, remove dead copper, pour order 14): 0,115 100,115 100,0 0,0

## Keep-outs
Keep-Out Layer:
  lines w0.254: -0.02,115 100,115 100,0 0,0 0,115

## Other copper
Top Layer:
  pour cut-out: 64.516,0 64.516,78.486 75.692,78.486 75.692,115 100,115 100,0
  pour cut-out: 0,79.35 14.453,79.35 14.453,64.897 0.051,64.897
Bottom Layer:
  pour cut-out: 64.643,0 64.516,0.127 64.516,78.486 75.692,78.486 75.692,114.96 100,115 100,0
  pour cut-out: 0,64.897 0,79.375 14.453,79.375 14.453,64.897

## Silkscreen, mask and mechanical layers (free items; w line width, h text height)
Top Overlay:
  lines w0.254: 2,10 21,10 21,35 2,35 2,10
Bottom Overlay:
  text "SS Focuser-B3" at -7.163,7.442 h0.89 r270
  text "www.kctw.cn" at -4.547,5.918 h0.89 r270

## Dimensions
100,115 to 100,0 on Top Overlay
0,0 to 100,0 on Top Overlay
